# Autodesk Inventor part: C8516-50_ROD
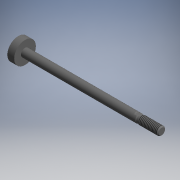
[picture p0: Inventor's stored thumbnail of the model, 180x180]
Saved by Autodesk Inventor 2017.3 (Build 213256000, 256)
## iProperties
Part Number: C8516-50_ROD
Material: Generic
Catalog Web Link: www.cadenas.de
Description: C85/CD85 ROD-ISO Standard Air Cylinder:Standard Type Double Acting Single Rod
Vendor: SMC
Document SubType Name: Modeling
Designer: partserver
Manufacturer: SMC
Mass: 3.82651 g
Surface Area: 25.4402 cm^2
Volume: 3.82651 cm^3
Density: 1 g/cm^3
Appearance: PSOLRGB-128-128-128
Category: PARTsolutions
Company: SMC
Title: C8516-50_ROD
Author: Cadenas PARTsolutions
Comments: ISO Standard Air Cylinder:Standard Type Double Acting Single Rod
PSOL_IDENT_0: {$CADENAS_DATA\23d-libs\smc_jp\actuator\standard_air_cylinder\c85\c85\parts\c85_rod.prj},195 {VTYP=3
PSOL_IDENT_1: D},{NB=C8516-50_ROD},{LINA=C8516-50_ROD},{NN=C85/CD85 ROD},{DATE=09.12.2020 03:32:11},{GEOMDATE=26.0
PSOL_IDENT_2: 4.2020 02:54:00},{VERSION=},{LINEID=40},{WBVAR=STROKE,CUSHION,BOOT},{WBNUMERIC=STROKE}  {NB=C8516-50
PSOL_IDENT_3: _ROD},{LINA=C8516-50_ROD},{KT=DUMMY},{ORDER=C8516-50},{BORE=16},{STROKE=50},{CUSHION=},{BOOT=},{BOOT
PSOL_IDENT_4: X='','N/A' },{AM=16},{C=6},{F=17},{H=38},{K=5},{KK=M6x1},{KKD=6},{KKJ=1.00},{N1=12.5},{WH=0},{MAX=40
PSOL_IDENT_5: 0},{X1=5.300},{X2=3.500},{KW=5.0}
NB: C8516-50_ROD
NN: C85/CD85 ROD
NT: ISO Standard Air Cylinder:Standard Type Double Acting Single Rod
NBSYN: $ORDER._ROD
LINA: C8516-50_ROD
CATALOG: SMC (JP
BORE: 16
STROKE: 50
CUSHION: (-) Rubber bumper(Standard)
BOOT: N/A
AM: 16
C: 6
K: 5
KK: M6x1
KKD: 6
KKJ: 1
MAX: 400
X1: 5.3
X2: 3.5
KW: 5
SUPPLIER: SMC
ARTICLENO: C8516-50_ROD
BOMINFO: C8516-50_ROD
CREATOR: CADENAS GmbH
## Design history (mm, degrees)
sketch "Sketch_1"
  geometry: L1 (67.5, 0)-(-38, 0); L2 (-38, 0)-(-38, 2.386); L3 (-38, 2.386)-(-37.386, 3); L4 (-37.386, 3)-(-23.5, 3); L5 (-23.5, 3)-(-23.5, 2.65); L6 (-23.5, 2.65)-(-22, 2.65); L7 (-22, 2.65)-(-21.394, 3); L8 (-21.394, 3)-(62.5, 3); L9 (62.5, 3)-(62.5, 8); L10 (62.5, 8)-(67.5, 8); L11 (67.5, 8)-(67.5, 0); L12 (67.5, 0)-(-38, 0)
  constraints: 24 end point
revolve "Revolution1" sketch "Sketch_1" stored, may be unused: angle "d0" = 360 deg
thread "Thread1" dims "d1" = 13.8865, "d2" = 0
sketch "Sketch_2"
  geometry: L1 (23.3, -7.5)-(23.3, -2.8); L2 (23.3, -2.8)-(23, -2.5); L3 (23, -2.5)-(19.5, -2.5); L4 (19.5, -2.5)-(14.5, -7.5); L5 (14.5, -7.5)-(23.3, -7.5)
  constraints: 10 end point
extrude "Extrusion1" cut sketch "Sketch_2" stored distance "d3" = 10; taper "d4" = 0 deg
sketch "Sketch_3"
  geometry: L1 (23.3, 7.5)-(14.5, 7.5); L2 (14.5, 7.5)-(19.5, 2.5); L3 (19.5, 2.5)-(23, 2.5); L4 (23, 2.5)-(23.3, 2.8); L5 (23.3, 2.8)-(23.3, 7.5)
  constraints: 10 end point
extrude "Extrusion2" cut sketch "Sketch_3" stored distance "d5" = 10; taper "d6" = 0 deg
node "ROD_BODY_XY"
node "ROD_BODY_YZ"
node "ROD_BODY_ZX"
node "ROD_BODY_X"
node "ROD_BODY_Y"
node "ROD_BODY_Z"
node "ROD_BODY_Center"
node "ROD_RODNUT_XY"
node "ROD_RODNUT_YZ"
node "ROD_RODNUT_ZX"
node "ROD_RODNUT_X"
node "ROD_RODNUT_Y"
node "ROD_RODNUT_Z"
node "ROD_RODNUT_Center"
node "Rod_Accessory_XY"
node "Rod_Accessory_YZ"
node "Rod_Accessory_ZX"
node "Rod_Accessory_X"
node "Rod_Accessory_Y"
node "Rod_Accessory_Z"
node "Rod_Accessory_Center"
body "Solid1"
